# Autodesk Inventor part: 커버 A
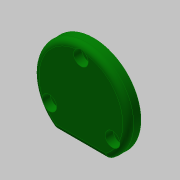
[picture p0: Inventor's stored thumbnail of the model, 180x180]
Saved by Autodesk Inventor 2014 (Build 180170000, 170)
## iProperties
Created: 2020-04
Part Number: 커버 A
Material: 알루미늄 6061
Document SubType Name: Modeling
Designer: mduedu
Density: 2.71 g/cm^3
Mass: 33.9278 g
Surface Area: 60.2978 cm^2
Volume: 12.5195 cm^3
Appearance: 진녹색
Author: mduedu
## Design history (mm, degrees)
sketch "스케치1"
  geometry: C1 r 26 at (0, 0); 1 further point
  constraints: 1 centre point, 1 coincident
  dimensions: "d0" = 52 diameter of C1
extrude "돌출1" new body sketch "스케치1" distance "d1" = 7; taper "d2" = 0 deg
sketch "스케치2"
  geometry: L1 (-14.62, -21.5)-(14.62, -21.5); A1 r 26 centre (0, 0) between (-14.62, -21.5) and (14.62, -21.5) reference; 1 further point
  constraints: 2 end point, 2 point on circle, 1 horizontal
  dimensions: "d3" = 21.5 distance from line of L1 point (0, 0)
extrude "돌출2" cut sketch "스케치2" stored distance "d4" = 7; taper "d5" = 0 deg
fillet "모깎기1" dims "d6" = 3
fillet "모깎기2" dims "d7" = 3
sketch "스케치3" dims "d8" = 40
  geometry: 3 further points
  constraints: 2 vertical alignment, 1 coincident, 2 other
hole "구멍1" sketch "스케치3" at (0, 20) diameter "d9" = 4.5; stored, may be unused: countersink angle "d13" = 90 deg, drill point angle "d15" = 118 deg; dims "d10" = 6, "d11" = 8, "d12" = 4.4, "d14" = 8
sketch "스케치4"
  geometry: C1 r 16 at (0, 0); 1 further point
  constraints: 1 centre point, 1 coincident
  dimensions: "d19" = 32 diameter of C1
extrude "돌출3" join sketch "스케치4" distance "d20" = 3; taper "d21" = 0 deg
sketch "스케치5"
  geometry: C1 r 14 at (0, 0); 1 further point
  constraints: 1 centre point, 1 coincident
  dimensions: "d22" = 28 diameter of C1
extrude "돌출4" cut sketch "스케치5" distance "d23" = 7; taper "d24" = 0 deg
fillet "모깎기3" dims "d25" = 3
chamfer "모따기1" distance "d26" = 0.5; stored, may be unused: second distance "d27" = 2, angle "d28" = 45 deg
node "솔리드1"
pattern_circular "원형 패턴1" dims angle "d17" = 360 deg
node "투영된 루프1"
